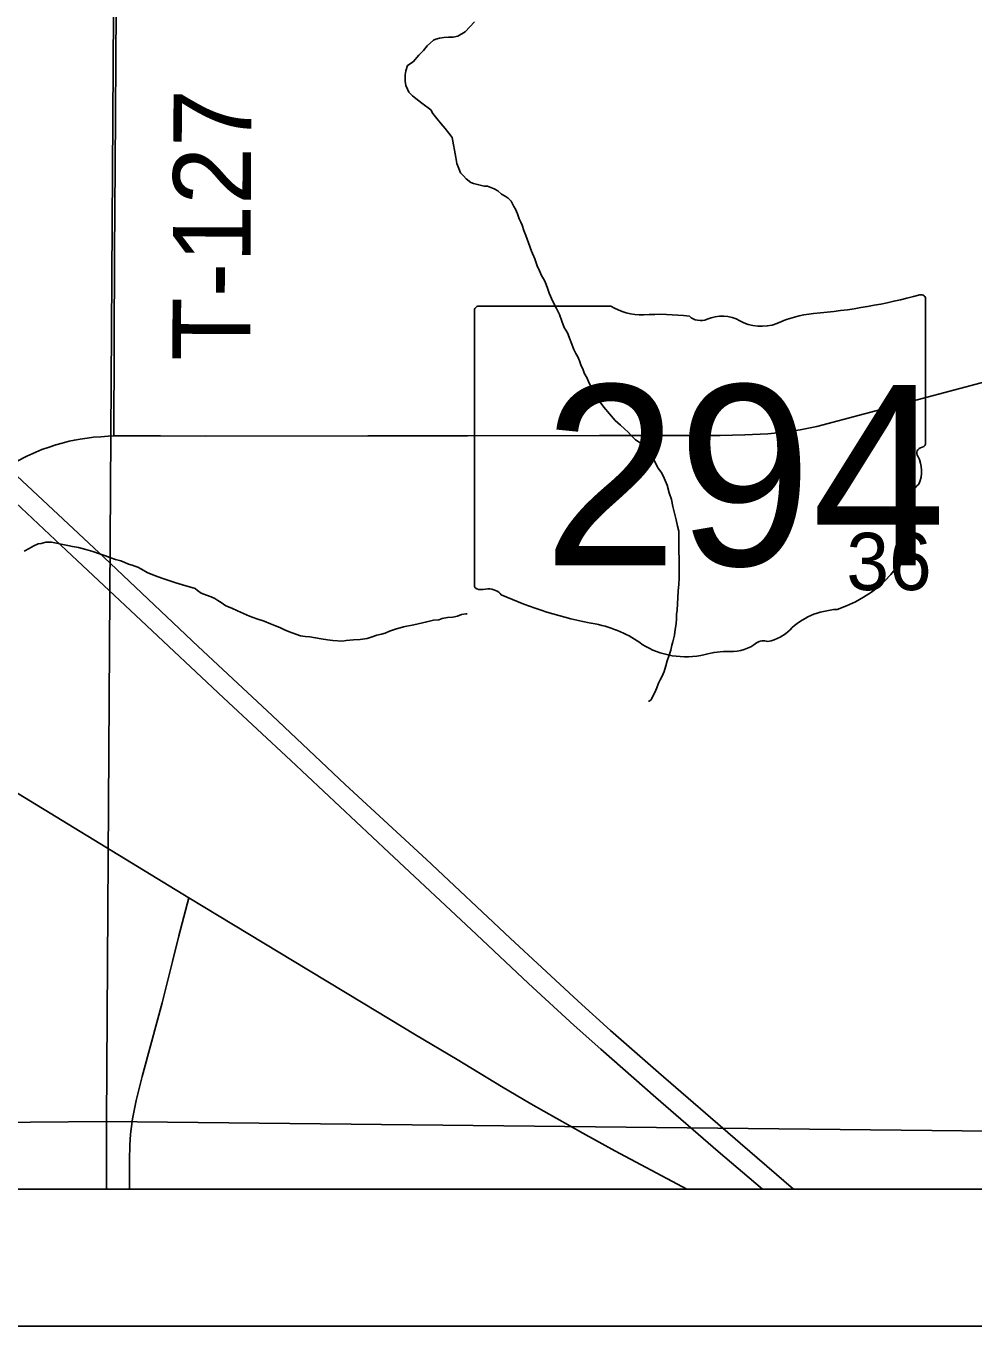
# Model space of a CAD drawing. Extents: x -17 to 88, y -5 to 22.
# Drawn here: x 7.649 to 8.342, y 14 to 14.95 of the extents above; entities that cross this region are included whole.
import ezdxf

# ---------------------------------------------------------------- set-up
doc = ezdxf.new("R2010")
doc.units = 0
for name, color, linetype in [('GM_X_County_Road', 7, 'Continuous'), ('GM_X_Minor_River', 7, 'Continuous'), ('GM_X_Section', 7, 'Continuous'), ('GM_X_Section_Text', 7, 'Continuous'), ('GM_X_State_Location', 7, 'Continuous'), ('GM_X_State_Route', 7, 'Continuous'), ('GM_X_State_Shield', 7, 'Continuous'), ('GM_X_Township', 7, 'Continuous'), ('GM_X_Township_Road', 7, 'Continuous'), ('GM_X_Township_Road_Text', 7, 'Continuous'), ('GM_X_US_Route', 7, 'Continuous'), ('SH_Data', 7, 'Continuous')]:
    doc.layers.add(name, color=color, linetype=linetype)

msp = doc.modelspace()

# ---------------------------------------------------------------- linework, layer by layer
at = {"layer": 'GM_X_County_Road'}
for points in [[(7.7683, 14.3128), (7.68455, 14.36403), (7.63944, 14.3915), (7.57509, 14.43041), (7.52832, 14.45879), (7.49286, 14.4806), (7.46153, 14.49967), (7.44626, 14.5093), (7.43495, 14.51702), (7.42537, 14.52397), (7.41704, 14.53053), (7.40994, 14.53663), (7.4022, 14.54388), (7.39527, 14.55107), (7.38752, 14.56003), (7.37898, 14.57075), (7.36625, 14.58763), (7.34919, 14.61056), (7.33354, 14.63148), (7.3224, 14.64718), (7.31914, 14.65159)], [(8.13196, 14.1), (8.1287, 14.10178), (8.0793, 14.12803), (8.05591, 14.14098), (8.01804, 14.16243), (7.99663, 14.17509), (7.96416, 14.19465), (7.93373, 14.21279), (7.89546, 14.23597), (7.85555, 14.26006), (7.7683, 14.3128)]]:
    msp.add_lwpolyline(points, dxfattribs=at)
at = {"layer": 'GM_X_Minor_River'}
for points in [[(7.97674, 14.95273), (7.96992, 14.94552), (7.9646, 14.94248), (7.96119, 14.94172), (7.95778, 14.94172), (7.95436, 14.94134), (7.95133, 14.94096), (7.94867, 14.9402), (7.94677, 14.93944), (7.94222, 14.93526), (7.93957, 14.93184), (7.93615, 14.92842), (7.93198, 14.92349), (7.92781, 14.92083), (7.92667, 14.91703), (7.92629, 14.91399), (7.92629, 14.91171), (7.92629, 14.90944), (7.92667, 14.9064), (7.92781, 14.90374), (7.92895, 14.90146), (7.9316, 14.89881), (7.93388, 14.89691), (7.93616, 14.89501), (7.93844, 14.89349), (7.94033, 14.89197), (7.94299, 14.89007), (7.94489, 14.88856), (7.94641, 14.8859), (7.94944, 14.8821), (7.95248, 14.8783), (7.95552, 14.87488), (7.95817, 14.87147), (7.96045, 14.86843), (7.96311, 14.85362), (7.96387, 14.84945), (7.96539, 14.84565), (7.96653, 14.84261), (7.96881, 14.84033), (7.97071, 14.83805), (7.97412, 14.8354), (7.97602, 14.83464), (7.97905, 14.83388), (7.98095, 14.8335), (7.98399, 14.83274), (7.98626, 14.83274), (7.9912, 14.83084), (7.99385, 14.82932), (7.99651, 14.82704), (7.99917, 14.82553), (8.00144, 14.82401), (8.00372, 14.82173), (8.00562, 14.81793), (8.00676, 14.81603), (8.00828, 14.81262), (8.00942, 14.80882), (8.01056, 14.80654), (8.0117, 14.80426), (8.01283, 14.80047), (8.01435, 14.79667), (8.01625, 14.79135), (8.01853, 14.78528), (8.02081, 14.77958), (8.02271, 14.77465), (8.02423, 14.77085), (8.02612, 14.76705), (8.02764, 14.76439), (8.02878, 14.76212), (8.02992, 14.75908), (8.03144, 14.75452)], [(8.03144, 14.75452), (8.0341, 14.74845), (8.03675, 14.74351), (8.03903, 14.73895), (8.04055, 14.73402), (8.04245, 14.72946), (8.04473, 14.72566), (8.04929, 14.71351), (8.0508, 14.71048), (8.05232, 14.7082), (8.05346, 14.70516), (8.0546, 14.70212), (8.05612, 14.6987), (8.05726, 14.69567), (8.05878, 14.69301), (8.06067, 14.68883), (8.0622, 14.6858), (8.06371, 14.68276), (8.06561, 14.67972), (8.06789, 14.67592), (8.07131, 14.67137), (8.07548, 14.66643), (8.07966, 14.66149), (8.08345, 14.65808), (8.08649, 14.65542), (8.08914, 14.65314), (8.09142, 14.65048), (8.09446, 14.64745), (8.09863, 14.64479), (8.10091, 14.64251), (8.10281, 14.63985), (8.10509, 14.6372), (8.10698, 14.63454), (8.1085, 14.6315), (8.11078, 14.62694), (8.11306, 14.62391), (8.11458, 14.62125), (8.1161, 14.61783), (8.11761, 14.61441), (8.11913, 14.60872), (8.12065, 14.60378), (8.12179, 14.59885), (8.12293, 14.59391), (8.12407, 14.58897), (8.12521, 14.58442), (8.12597, 14.58062), (8.12597, 14.57492), (8.12597, 14.56923), (8.12597, 14.56543), (8.12636, 14.56125), (8.12636, 14.55745), (8.12636, 14.55404), (8.12636, 14.54986), (8.12636, 14.54644), (8.12598, 14.54189), (8.1256, 14.53695), (8.12485, 14.5229), (8.12447, 14.51986), (8.12447, 14.51682), (8.12409, 14.51303), (8.12334, 14.50885), (8.12296, 14.50467), (8.12182, 14.49974), (8.12106, 14.49746), (8.1203, 14.49366), (8.11879, 14.48948), (8.11765, 14.48606), (8.11651, 14.48227), (8.11538, 14.47809), (8.11386, 14.47467), (8.11234, 14.47201), (8.1112, 14.46974), (8.11007, 14.46632), (8.10855, 14.4629), (8.10703, 14.46024), (8.10589, 14.45758), (8.10438, 14.45644), (8.104, 14.45682)], [(7.64787, 14.56612), (7.65167, 14.56802), (7.65508, 14.56992), (7.65811, 14.57144), (7.66039, 14.57182), (7.66381, 14.57258), (7.66798, 14.57258), (7.67974, 14.5703), (7.68316, 14.56954), (7.68771, 14.56878), (7.69302, 14.56727), (7.69796, 14.56575), (7.70289, 14.56423), (7.70744, 14.56271), (7.71048, 14.56157), (7.71465, 14.56006), (7.71845, 14.55892), (7.72149, 14.55778), (7.72414, 14.55664), (7.7268, 14.55588), (7.7287, 14.55512), (7.73097, 14.55436), (7.73363, 14.55284)], [(7.73363, 14.55284), (7.7378, 14.55056), (7.74312, 14.54829), (7.74919, 14.54601), (7.75867, 14.54297), (7.76589, 14.5407), (7.77044, 14.53956), (7.77271, 14.5388), (7.77461, 14.53728), (7.77727, 14.53538), (7.78106, 14.53386), (7.78448, 14.53272), (7.78714, 14.53158), (7.78941, 14.53007), (7.79169, 14.52855), (7.7951, 14.52627), (7.79966, 14.52437), (7.80383, 14.52247), (7.80801, 14.52057), (7.81256, 14.51868), (7.81788, 14.51678), (7.82319, 14.51488), (7.82774, 14.51298), (7.83154, 14.51146), (7.83457, 14.51033), (7.83761, 14.50881), (7.84102, 14.50729), (7.84634, 14.50539), (7.84975, 14.50425), (7.85317, 14.50387), (7.85658, 14.50349), (7.86076, 14.50274), (7.86493, 14.50198), (7.86948, 14.50122), (7.87328, 14.50084), (7.88049, 14.50046), (7.88314, 14.50084), (7.88846, 14.50122), (7.89339, 14.5016), (7.89832, 14.50236), (7.90212, 14.5035), (7.90553, 14.50464), (7.90894, 14.5054), (7.9116, 14.50616), (7.91464, 14.50768), (7.91919, 14.5092), (7.92488, 14.51072), (7.93247, 14.51224), (7.94196, 14.51452), (7.94689, 14.51566), (7.95068, 14.51604), (7.95334, 14.5168), (7.95713, 14.51756), (7.96093, 14.51794), (7.96434, 14.5187), (7.96738, 14.51984), (7.97041, 14.52022), (7.97155, 14.52022)]]:
    msp.add_lwpolyline(points, dxfattribs=at)
at = {"layer": 'GM_X_Section'}
for p, q in [((6.70958, 14.1), (7.70796, 14.1)), ((7.70796, 14.1), (8.7123, 14.1))]:
    msp.add_line(p, q, dxfattribs=at)
for points in [[(6.71014, 15.14163), (7.71436, 15.15219), (7.70793, 14.14937), (6.70992, 14.1406)], [(7.71436, 15.15219), (8.72055, 15.1393), (8.71261, 14.13838), (7.70793, 14.14937)]]:
    msp.add_lwpolyline(points, close=True, dxfattribs=at)
for points in [[(7.70796, 14.1), (7.70793, 14.14937), (6.70992, 14.1406), (6.70958, 14.1)], [(8.7123, 14.1), (8.71261, 14.13838), (7.70793, 14.14937), (7.70796, 14.1)]]:
    msp.add_lwpolyline(points, dxfattribs=at)
at = {"layer": 'GM_X_State_Route'}
for points in [[(7.72537, 14.65046), (7.74739, 14.65031), (7.78033, 14.65023), (7.89904, 14.65037), (7.97174, 14.65044), (8.06807, 14.65059), (8.11282, 14.65049), (8.15633, 14.65064), (8.17437, 14.651), (8.19117, 14.65184), (8.20359, 14.65298), (8.2147, 14.65464), (8.22689, 14.65729), (8.26174, 14.66654), (8.33142, 14.68505), (8.38068, 14.69812)], [(7.63523, 14.62805), (7.64979, 14.6354), (7.65646, 14.63845), (7.66073, 14.64026), (7.66616, 14.64215), (7.67101, 14.64371), (7.67577, 14.64511), (7.68079, 14.64643), (7.68465, 14.64725), (7.68885, 14.648), (7.69394, 14.64874), (7.69863, 14.64931), (7.70381, 14.64972), (7.70932, 14.65005), (7.71336, 14.65025), (7.72254, 14.65047), (7.72537, 14.65046)]]:
    msp.add_lwpolyline(points, dxfattribs=at)
at = {"layer": 'GM_X_State_Shield'}
for p, q in [((7.97675, 14.74168), (7.97675, 14.54156)), ((8.07652, 14.74513), (7.98, 14.74513)), ((8.30634, 14.6454), (8.30634, 14.75008)), ((8.3063, 14.64542), (8.30634, 14.6454))]:
    msp.add_line(p, q, dxfattribs=at)
for centre, major_axis, start_param, end_param in [((8.18893, 15.01796), (0.34952, 0), 4.814394, 5.042369), ((8.30268, 14.75052), (0.00367, 0), 6.141152, 7.989035), ((7.98053, 14.74211), (0.00382, 0), 1.712693, 3.28349), ((8.0995, 14.76836), (0.03703, 0), 4.042523, 4.731795), ((8.11178, 14.63278), (0.13295, 0), 1.404758, 1.657858), ((8.14197, 14.74315), (0.01068, 0), 3.836095, 5.185415), ((8.15765, 14.72002), (0.02221, 0), 0.950623, 2.079405), ((8.18632, 14.75174), (0.02672, 0), 4.081561, 5.145723), ((8.23352, 14.684), (0.07032, 0), 1.699011, 2.107814), ((8.30549, 14.63771), (0.00568, 0), 1.883978, 3.671073), ((8.30242, 14.64499), (0.00393, 0), 5.05454, 6.418171), ((8.26936, 14.62448), (0.03409, 0), 5.934695, 6.695948), ((8.31948, 14.60159), (0.0248, 0), 2.387724, 3.262537), ((8.20851, 14.58827), (0.08742, 0), 5.101752, 6.440018), ((7.98056, 14.54112), (0.00385, 0), 3.00124, 4.508301), ((7.98115, 14.5616), (0.0294, 0), 4.665946, 4.897461), ((7.98716, 14.53002), (0.0106, 0), 0.519207, 1.627899), ((8.12099, 14.70982), (0.2524, 0), 4.195997, 4.488961), ((8.24537, 14.48538), (0.04788, 0), 1.647645, 2.488434), ((8.04574, 14.45166), (0.07897, 0), 0.823519, 1.323587), ((8.18471, 14.52217), (0.02824, 0), 4.937069, 5.64225), ((8.13115, 14.52902), (0.05011, 0), 4.026481, 4.996735), ((8.16376, 14.51404), (0.0267, 0), 4.691044, 5.507374), ((8.18792, 14.49466), (0.00752, 0), 1.147584, 2.315152), ((8.1601, 14.45983), (0.04118, 0), 1.495662, 1.94098)]:
    msp.add_ellipse(centre, major_axis=major_axis, ratio=0.8, start_param=start_param, end_param=end_param, dxfattribs=at)
at = {"layer": 'GM_X_Township'}
msp.add_line((2.60501, 14.1), (8.70899, 14.1), dxfattribs=at)
at = {"layer": 'GM_X_Township_Road'}
for points in [[(7.71336, 14.65025), (7.71386, 14.78366), (7.71427, 14.84766), (7.71511, 14.96262), (7.7155, 15.01979), (7.71649, 15.11362), (7.71707, 15.2118), (7.71711, 15.28948), (7.71703, 15.32242), (7.71688, 15.35933)], [(7.72476, 14.1), (7.72476, 14.10346), (7.72473, 14.1215), (7.72508, 14.13207), (7.72565, 14.14014), (7.72694, 14.15128), (7.72963, 14.16473), (7.7341, 14.1822), (7.74099, 14.20739), (7.7486, 14.23622), (7.75617, 14.26635), (7.76091, 14.28503), (7.7683, 14.3128)]]:
    msp.add_lwpolyline(points, dxfattribs=at)
at = {"layer": 'GM_X_US_Route'}
for points in [[(8.18722, 14.1), (8.15487, 14.12747), (8.10929, 14.16692), (8.06913, 14.20218), (8.04971, 14.21961), (8.01633, 14.25032), (7.97828, 14.28606), (7.91432, 14.34597), (7.87858, 14.37963), (7.8427, 14.41316), (7.79356, 14.45888), (7.7334, 14.51556), (7.67889, 14.56647), (7.62055, 14.62121), (7.56741, 14.67109), (7.51901, 14.71669), (7.47864, 14.75451), (7.42288, 14.8068), (7.38192, 14.8449), (7.34343, 14.88107), (7.29384, 14.92814), (7.22063, 14.99635)], [(8.2099, 14.1), (8.17081, 14.13359), (8.11111, 14.18522), (8.07609, 14.21601), (8.05255, 14.23728), (8.00285, 14.28332), (7.94178, 14.34086), (7.88247, 14.39574), (7.82911, 14.44605), (7.77501, 14.49649), (7.70643, 14.56146), (7.63523, 14.62805)]]:
    msp.add_lwpolyline(points, dxfattribs=at)
at = {"layer": 'SH_Data'}
for p, q in [((2.6, 14.1), (9.4, 14.1)), ((2.5, 14), (9.5, 14))]:
    msp.add_line(p, q, dxfattribs=at)

# ---------------------------------------------------------------- texts
at = {"layer": 'GM_X_Section_Text'}
msp.add_text('36', height=0.041856, rotation=0.00001, dxfattribs=at).set_placement((8.24848, 14.53765))
at = {"layer": 'GM_X_State_Location'}
for s in ['s', 'r']:
    msp.add_text(s, height=0.000189, dxfattribs=at).set_placement((8.13784, 14.62832))
msp.add_text('294', height=0.000189, rotation=0.00001, dxfattribs=at).set_placement((8.07098, 14.61454))
at = {"layer": 'GM_X_State_Shield'}
msp.add_text('294', height=0.131836, dxfattribs=at).set_placement((8.02708, 14.55567))
at = {"layer": 'GM_X_Township_Road_Text'}
msp.add_text('T-127', height=0.056818, rotation=89.7281, dxfattribs=at).set_placement((7.81293, 14.70502))

doc.saveas('drawing.dxf')
